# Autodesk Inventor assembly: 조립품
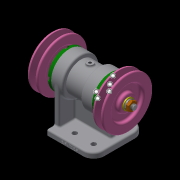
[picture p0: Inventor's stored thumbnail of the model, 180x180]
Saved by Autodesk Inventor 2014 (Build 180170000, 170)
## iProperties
Created: 2020-06
Part Number: 조립품
Document SubType Name: Assembly
Designer: kh
Author: kh
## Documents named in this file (12)
- C:\Users\kh\Desktop\700606V1045\조립품.iam
- C:\Users\kh\Desktop\700606V1045\본체.ipt
- C:\Users\kh\Desktop\700606V1045\베어링 6204.ipt
- C:\Users\kh\Desktop\700606V1045\커버.ipt
- C:\Users\kh\Desktop\700606V1045\볼트 M4.ipt
- C:\Users\kh\Desktop\700606V1045\축.ipt
- C:\Users\kh\Desktop\700606V1045\키 5x5x12.ipt
- C:\Users\kh\Desktop\700606V1045\커버_MIR.ipt
- C:\Users\kh\Desktop\700606V1045\V-벨트풀리.ipt
- C:\Users\kh\Desktop\700606V1045\스프링 와셔 10.ipt
- C:\Users\kh\Desktop\700606V1045\평면 와셔 10x21.ipt
- C:\Users\kh\Desktop\700606V1045\너트 M10.ipt
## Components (2 placed, 1 different names)
1. V-벨트풀리:1 — Mate:18, Mate:19, Mate:20, Mate:28
2. V-벨트풀리:2 — Mate:24, Mate:25, Mate:26, Mate:34
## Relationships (8: Mate 8)
- Mate:18: V-벨트풀리:1
- Mate:19: V-벨트풀리:1
- Mate:20: V-벨트풀리:1
- Mate:24: V-벨트풀리:2
- Mate:25: V-벨트풀리:2
- Mate:26: V-벨트풀리:2
- Mate:28: V-벨트풀리:1
- Mate:34: V-벨트풀리:2
